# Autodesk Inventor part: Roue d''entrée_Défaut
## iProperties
Shininess: 64.0
Length Units: 11269
Angle Units: 11279
Time Units: 11290
Mass Units: 11283
Length Display Precision: 3
Angle Display Precision: 2
Compacted: True
Part Number: Roue d''entrée_Défaut
Document SubType Name: Modeling
Created: 2006-01
Material: Par défaut
Designer: riri
Density: 0.0
Volumn: 0.0
Area: 0.0
PropertySet Name: Model Information
Control State: 0
Master: False
Checked Out: False
Author: riri
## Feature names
1. Base1
